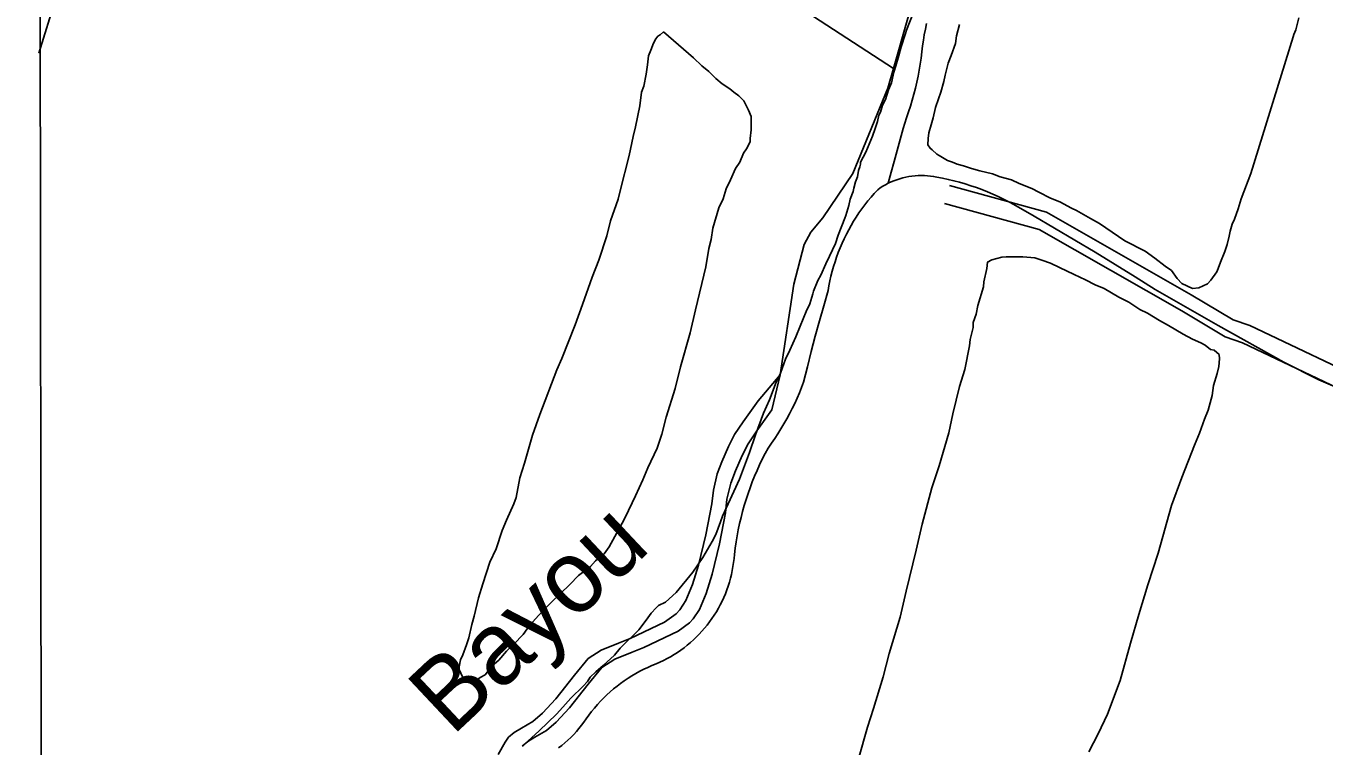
# Model space of a CAD drawing. Extents: x 3329332 to 3367211, y 631066 to 656469.
# Drawn here: x 3333430 to 3335509, y 637897 to 639050 of the extents above; entities that cross this region are included whole.
import ezdxf

# ---------------------------------------------------------------- set-up
doc = ezdxf.new("R2010")
doc.units = 0
for name, color, linetype in [('V-DTCH-CNTR', 7, 'Continuous'), ('V-GRID-FRAM', 7, 'Continuous'), ('V-RIVR-IDEN', 7, 'Continuous'), ('V-ROAD-CNTR', 7, 'Continuous'), ('V-SITE-VEGE', 7, 'Continuous'), ('V-TOPO-SHOR', 7, 'Continuous')]:
    doc.layers.add(name, color=color, linetype=linetype)

msp = doc.modelspace()

# ---------------------------------------------------------------- linework, layer by layer
at = {"layer": 'V-DTCH-CNTR'}
for points in [[(3334810.8, 638798.4), (3334815.4, 638816), (3334820.1, 638833.5), (3334824.8, 638851), (3334829.7, 638868.5), (3334834.7, 638886), (3334839.8, 638903.4), (3334843.1, 638912.7), (3334846.2, 638922.1), (3334849.2, 638931.5), (3334851.9, 638941), (3334854.3, 638950.5), (3334856.6, 638960.1), (3334858.7, 638969.8), (3334860.5, 638979.5), (3334862.1, 638989.2), (3334863.6, 638999), (3334864.7, 639008.8), (3334865.7, 639018.6), (3334867, 639027.5), (3334868.5, 639036.4), (3334870.3, 639045.3), (3334872.2, 639054.1)], [(3335238.4, 638628.4), (3335206.4, 638648.4), (3335174.3, 638668.2), (3335142, 638687.9), (3335109.7, 638707.3), (3335077.2, 638726.5), (3335044.6, 638745.6), (3335011.9, 638764.4), (3335003.6, 638768.9), (3334995.3, 638773.2), (3334986.8, 638777.3), (3334978.2, 638781.2), (3334969.5, 638784.8), (3334960.8, 638788.3), (3334952, 638791.6), (3334943.1, 638794.6), (3334934.1, 638797.4), (3334925, 638800.1), (3334915.9, 638802.5), (3334906.8, 638804.6), (3334897.6, 638806.6), (3334888.3, 638808.4), (3334883.4, 638809.3), (3334878.5, 638810), (3334873.6, 638810.5), (3334868.6, 638810.8), (3334863.6, 638810.9), (3334858.7, 638810.8), (3334853.7, 638810.4), (3334848.7, 638809.9), (3334843.8, 638809.2), (3334838.9, 638808.2), (3334834.1, 638807.1), (3334829.3, 638805.7), (3334824.6, 638804.2), (3334819.9, 638802.5), (3334815.3, 638800.5), (3334810.8, 638798.4), (3334806.4, 638796.1), (3334802.1, 638793.6), (3334797.9, 638790.9), (3334793.8, 638788.1), (3334788.4, 638782.3), (3334783.2, 638776.3), (3334778.1, 638770.2), (3334773.2, 638763.9), (3334768.5, 638757.5), (3334763.9, 638751), (3334759.5, 638744.4), (3334755.3, 638737.7), (3334751.2, 638730.8), (3334747.4, 638723.9), (3334743.7, 638716.8), (3334740.2, 638709.7), (3334736.8, 638702.5), (3334733.7, 638695.2), (3334730.8, 638687.8), (3334728, 638680.3), (3334725.5, 638672.8), (3334723.1, 638665.2), (3334721, 638657.6), (3334719, 638649.9), (3334717.3, 638642.1), (3334715.7, 638634.3), (3334714.4, 638626.5)], [(3334714.4, 638626.5), (3334707.4, 638602.2), (3334700.5, 638577.9), (3334693.9, 638553.5), (3334687.4, 638529.1), (3334681.2, 638504.7), (3334675, 638480.2), (3334671.8, 638471.5), (3334668.4, 638462.9), (3334664.8, 638454.3), (3334661, 638445.9), (3334657, 638437.5), (3334652.8, 638429.3), (3334648.4, 638421.1), (3334643.8, 638413.1), (3334639, 638405.1), (3334634.1, 638397.3), (3334628.9, 638389.6), (3334623.6, 638382), (3334618.2, 638374.5), (3334613.5, 638365.7), (3334609, 638356.8), (3334604.7, 638347.8), (3334600.6, 638338.7), (3334596.7, 638329.5), (3334593, 638320.2), (3334589.5, 638310.8), (3334586.2, 638301.4), (3334583.1, 638291.9), (3334580.2, 638282.4), (3334577.5, 638272.8), (3334575, 638263.1), (3334572.7, 638253.4), (3334570.6, 638243.6), (3334568.7, 638233.8), (3334567, 638224), (3334565.6, 638214.1), (3334564.3, 638204.2), (3334563.8, 638197.7), (3334563.1, 638191.3), (3334562.1, 638184.9), (3334561, 638178.5), (3334559.6, 638172.1), (3334558.1, 638165.8), (3334556.4, 638159.6), (3334554.4, 638153.4), (3334552.3, 638147.3), (3334550, 638141.2), (3334547.4, 638135.2), (3334544.7, 638129.3), (3334541.8, 638123.5), (3334538.8, 638117.8), (3334535.5, 638112.2), (3334532.1, 638106.7), (3334528.5, 638101.3), (3334524.7, 638096), (3334520.8, 638090.9), (3334516.7, 638085.9), (3334512.4, 638081), (3334508, 638076.2), (3334503.4, 638071.6), (3334498.7, 638067.1), (3334493.9, 638062.8), (3334488.9, 638058.7), (3334483.8, 638054.7), (3334478.6, 638050.8), (3334473.2, 638047.1), (3334467.8, 638043.7), (3334462.2, 638040.3), (3334456.5, 638037.2), (3334450.8, 638034.2), (3334444.9, 638031.4), (3334439, 638028.9), (3334432.3, 638026.2), (3334425.7, 638023.2), (3334419.1, 638020.1), (3334412.7, 638016.9), (3334406.4, 638013.4), (3334400.2, 638009.7), (3334394.1, 638005.9), (3334388.1, 638001.8), (3334382.2, 637997.6), (3334376.5, 637993.2), (3334370.9, 637988.7), (3334365.4, 637984), (3334360.1, 637979.1), (3334354.9, 637974.1), (3334349.8, 637968.9), (3334345, 637963.6), (3334340.2, 637958.1), (3334335.7, 637952.5), (3334331.3, 637946.8), (3334327.1, 637940.9), (3334323.4, 637935.6), (3334319.6, 637930.4), (3334315.5, 637925.4)], [(3335238.4, 638628.4), (3335339.3, 638570.5), (3335444.3, 638511.7), (3335500.3, 638483.7), (3335530.1, 638470.7), (3335576.5, 638452.5), (3335626.4, 638433.6), (3335714.4, 638405.1), (3335800.5, 638379.4), (3335853.2, 638361.9)], [(3334315.5, 637925.4), (3334311.3, 637920.4), (3334307, 637915.7), (3334302.5, 637911), (3334297.8, 637906.6), (3334293, 637902.2), (3334288, 637898.1), (3334282.9, 637894.1)]]:
    msp.add_lwpolyline(points, dxfattribs=at)
at = {"layer": 'V-GRID-FRAM'}
msp.add_lwpolyline([(3333429.9, 654632), (3364987.9, 654691.7), (3365030.2, 636507.7), (3333456.4, 636448), (3333429.9, 654632)], dxfattribs=at)
at = {"layer": 'V-ROAD-CNTR'}
for points in [[(3333450.3, 639006.7), (3333532.2, 639270.1), (3333696.4, 639772.9), (3333708.4, 639832.1), (3333708.2, 639866.7), (3333693, 639907.9), (3333671.2, 639941.2), (3333642, 639975.6), (3333448.6, 640213.1)], [(3333450.3, 639006.7), (3333450.3, 639006.7)], [(3333450.3, 639006.7), (3333450.3, 639006.7)], [(3333450.3, 639006.7), (3333450.3, 639006.7)], [(3333450.3, 639006.7), (3333450.3, 639006.7)], [(3333450.3, 639006.7), (3333450.3, 639006.7)], [(3333450.3, 639006.7), (3333450.3, 639006.7)], [(3333450.3, 639006.7), (3333450.3, 639006.7)], [(3333450.3, 639006.7), (3333450.3, 639006.7)], [(3334908.9, 638794.7), (3335064.2, 638752.3), (3335295.8, 638620), (3335363.2, 638579.9), (3335389.5, 638570.7), (3335596.2, 638472.2), (3335773.9, 638408.5), (3335858, 638383.2), (3335928.9, 638357.3), (3336079.5, 638310.9), (3336242.2, 638252.3), (3336363.2, 638197.5), (3336453.2, 638180.6), (3336572, 638138.2), (3336799.2, 638066.7), (3337035.2, 637993.3), (3337050.7, 637983.7)], [(3334901, 638765.8), (3335052.6, 638724.4), (3335280.7, 638594.1), (3335350.5, 638552.6), (3335378.1, 638542.9), (3335584.7, 638444.5), (3335764.5, 638380), (3335848.5, 638354.7), (3335919.4, 638328.9), (3336070, 638282.4), (3336230.9, 638224.5), (3336354.1, 638168.7), (3336445.4, 638151.6), (3336562.5, 638109.8), (3336790.2, 638038.1), (3337022.6, 637965.8), (3337032.8, 637959.5)]]:
    msp.add_lwpolyline(points, dxfattribs=at)
at = {"layer": 'V-SITE-VEGE'}
for p, q in [((3333455.7, 636954.7), (3333452.1, 639386.2)), ((3334850.4, 639070.8), (3334839.8, 639043.8)), ((3334445.4, 639036.3), (3334441.9, 639034.1)), ((3334451.1, 639040.7), (3334445.4, 639036.3)), ((3334499, 638999.3), (3334451.1, 639040.7)), ((3334838.6, 639038.2), (3334831.5, 639016.8)), ((3334839.8, 639043.8), (3334838.6, 639038.2)), ((3334435, 639022.9), (3334430.3, 639011.7)), ((3334438.5, 639029.6), (3334435, 639022.9)), ((3334441.9, 639034.1), (3334438.5, 639029.6)), ((3334831.5, 639016.8), (3334827.9, 639003.3)), ((3334426.8, 639002.7), (3334425.4, 638988)), ((3334430.3, 639011.7), (3334426.8, 639002.7)), ((3334512.4, 638986.7), (3334499, 638999.3)), ((3334827.9, 639003.3), (3334823.1, 638986.4)), ((3334422.9, 638973.4), (3334419.2, 638954.2)), ((3334425.4, 638988), (3334422.9, 638973.4)), ((3334523.6, 638977.5), (3334512.4, 638986.7)), ((3334534.7, 638966), (3334523.6, 638977.5)), ((3334819.6, 638976.3), (3334816, 638959.4)), ((3334823.1, 638986.4), (3334819.6, 638976.3)), ((3334419.2, 638954.2), (3334415.7, 638944.1)), ((3334544.7, 638957.9), (3334534.7, 638966)), ((3334557, 638949.8), (3334544.7, 638957.9)), ((3334816, 638959.4), (3334811.3, 638948.2)), ((3334415.7, 638944.1), (3334413.1, 638922.7)), ((3334563.7, 638944.1), (3334557, 638949.8)), ((3334571.5, 638938.3), (3334563.7, 638944.1)), ((3334579.3, 638930.3), (3334571.5, 638938.3)), ((3334806.5, 638932.4), (3334801.8, 638923.5)), ((3334811.3, 638948.2), (3334806.5, 638932.4)), ((3334413.1, 638922.7), (3334405.8, 638888.9)), ((3334587, 638915.5), (3334579.3, 638930.3)), ((3334591.4, 638905.2), (3334587, 638915.5)), ((3334798.3, 638912.2), (3334795.9, 638907.7)), ((3334801.8, 638923.5), (3334798.3, 638912.2)), ((3334591, 638883.8), (3334591.4, 638905.2)), ((3334793.5, 638897.6), (3334790, 638886.4)), ((3334795.9, 638907.7), (3334793.5, 638897.6)), ((3334402.2, 638873.1), (3334396.1, 638842.7)), ((3334405.8, 638888.9), (3334402.2, 638873.1)), ((3334589.6, 638864.6), (3334589.7, 638870.2)), ((3334589.7, 638870.2), (3334591, 638883.8)), ((3334785.3, 638874), (3334774.7, 638848.2)), ((3334790, 638886.4), (3334785.3, 638874)), ((3334579.2, 638846.7), (3334583.8, 638853.4)), ((3334583.8, 638853.4), (3334589.6, 638864.6)), ((3334774.7, 638848.2), (3334766.5, 638832.5)), ((3334396.1, 638842.7), (3334381.6, 638786.4)), ((3334566.4, 638822), (3334573.3, 638832.1)), ((3334573.3, 638832.1), (3334579.2, 638846.7)), ((3334766.5, 638829.1), (3334765.3, 638824.6)), ((3334766.5, 638832.5), (3334766.5, 638829.1)), ((3334558.2, 638804), (3334566.4, 638822)), ((3334761.7, 638808.8), (3334758.1, 638801)), ((3334762.9, 638819), (3334761.7, 638808.8)), ((3334765.3, 638824.6), (3334762.9, 638819)), ((3334381.6, 638786.4), (3334378, 638772.9)), ((3334546.4, 638773.7), (3334551.2, 638789.5)), ((3334551.2, 638789.5), (3334558.2, 638804)), ((3334754.5, 638785.2), (3334749.8, 638772.9)), ((3334755.7, 638790.8), (3334754.5, 638785.2)), ((3334758.1, 638801), (3334755.7, 638790.8)), ((3334378, 638772.9), (3334366.2, 638738.1)), ((3334539.4, 638759.1), (3334546.4, 638773.7)), ((3334749.8, 638772.9), (3334747.4, 638762.7)), ((3334529.9, 638726.5), (3334539.4, 638759.1)), ((3334742.6, 638747), (3334741.4, 638742.5)), ((3334747.4, 638762.7), (3334742.6, 638747)), ((3334366.2, 638738.1), (3334360.2, 638714.4)), ((3334527.3, 638708.5), (3334529.9, 638726.5)), ((3334741.4, 638742.5), (3334730.8, 638715.5)), ((3334360.2, 638714.4), (3334347.1, 638675.1)), ((3334523.7, 638693.8), (3334527.3, 638708.5)), ((3334726.1, 638702), (3334716.8, 638681.8)), ((3334730.8, 638715.5), (3334726.1, 638702)), ((3334518.7, 638664.5), (3334523.7, 638693.8)), ((3334716.8, 638681.8), (3334710.9, 638669.5)), ((3334347.1, 638675.1), (3334336.6, 638648.1)), ((3334501.9, 638595.9), (3334518.7, 638664.5)), ((3334710.9, 638669.5), (3334702.7, 638651.5)), ((3334336.6, 638648.1), (3334321.2, 638604.3)), ((3334698.1, 638642.6), (3334691, 638625.7)), ((3334702.7, 638651.5), (3334698.1, 638642.6)), ((3334689.8, 638621.2), (3334685.1, 638605.5)), ((3334691, 638625.7), (3334689.8, 638621.2)), ((3334321.2, 638604.3), (3334309.4, 638571.7)), ((3334685.1, 638605.5), (3334679.2, 638593.1)), ((3334493.4, 638558.7), (3334501.9, 638595.9)), ((3334679.2, 638593.1), (3334669.8, 638569.5)), ((3334309.4, 638571.7), (3334288.2, 638517.8)), ((3334477.9, 638504.7), (3334493.4, 638558.7)), ((3334669.8, 638569.5), (3334662.8, 638552.7)), ((3334662.8, 638552.7), (3334653.4, 638531.4)), ((3334288.2, 638517.8), (3334280, 638499.8)), ((3334646.4, 638516.8), (3334638.2, 638494.3)), ((3334653.4, 638531.4), (3334646.4, 638516.8)), ((3334280, 638499.8), (3334252.9, 638427.9)), ((3334469.4, 638469.8), (3334477.9, 638504.7)), ((3334638.2, 638494.3), (3334631.2, 638479.7)), ((3334631.2, 638479.7), (3334620.6, 638451.7)), ((3334455.2, 638423.7), (3334469.4, 638469.8)), ((3334620.6, 638451.7), (3334611.2, 638430.3)), ((3334252.9, 638427.9), (3334241.1, 638395.3)), ((3334448, 638396.7), (3334455.2, 638423.7)), ((3334611.2, 638430.3), (3334598.2, 638395.5)), ((3334241.1, 638395.3), (3334228, 638350.3)), ((3334440.8, 638374.2), (3334448, 638396.7)), ((3334598.2, 638395.5), (3334588.8, 638367.4)), ((3334425.7, 638342.8), (3334440.8, 638374.2)), ((3334228, 638350.3), (3334220.9, 638326.7)), ((3334588.8, 638367.4), (3334572.3, 638324.7)), ((3334417.5, 638323.7), (3334425.7, 638342.8)), ((3334220.9, 638326.7), (3334214.7, 638295.2)), ((3334405.8, 638297.9), (3334417.5, 638323.7)), ((3334572.3, 638324.7), (3334545.4, 638265.2)), ((3334214.7, 638295.2), (3334211.2, 638285)), ((3334389.4, 638263.1), (3334405.8, 638297.9)), ((3334211.2, 638285), (3334199.5, 638259.2)), ((3334199.5, 638259.2), (3334192.5, 638242.4)), ((3334363.8, 638216), (3334384.8, 638254.1)), ((3334384.8, 638254.1), (3334389.4, 638263.1)), ((3334541.9, 638256.2), (3334534.8, 638236)), ((3334545.4, 638265.2), (3334541.9, 638256.2)), ((3334192.5, 638242.4), (3334183, 638213.2)), ((3334528.9, 638224.8), (3334513.9, 638199)), ((3334534.8, 638236), (3334528.9, 638224.8)), ((3334183, 638213.2), (3334172.5, 638191.9)), ((3334342, 638193.8), (3334355.7, 638204.9)), ((3334355.7, 638204.9), (3334363.8, 638216)), ((3334172.5, 638191.9), (3334161.8, 638157)), ((3334314.5, 638170.5), (3334334, 638184.9)), ((3334334, 638184.9), (3334342, 638193.8)), ((3334513.9, 638199), (3334497.7, 638175.6)), ((3334300.8, 638156), (3334314.5, 638170.5)), ((3334497.7, 638175.6), (3334471.2, 638143.2)), ((3334161.8, 638157), (3334154.6, 638134.5)), ((3334270.9, 638127.1), (3334300.8, 638156)), ((3334471.2, 638143.2), (3334454, 638127.6)), ((3334154.6, 638134.5), (3334147.4, 638105.2)), ((3334251.4, 638107), (3334270.9, 638127.1)), ((3334442.6, 638122.2), (3334439.2, 638118.8)), ((3334454, 638127.6), (3334442.6, 638122.2)), ((3334147.4, 638105.2), (3334143.8, 638091.7)), ((3334236.5, 638090.3), (3334251.4, 638107)), ((3334431.1, 638109.9), (3334423, 638098.7)), ((3334439.2, 638118.8), (3334431.1, 638109.9)), ((3334143.8, 638091.7), (3334139, 638070.3)), ((3334226.1, 638075.8), (3334236.5, 638090.3)), ((3334411.5, 638083.1), (3334381.7, 638054.2)), ((3334423, 638098.7), (3334411.5, 638083.1)), ((3334135.4, 638059.1), (3334129.5, 638043.3)), ((3334139, 638070.3), (3334135.4, 638059.1)), ((3334199.7, 638049.1), (3334211.1, 638060.2)), ((3334211.1, 638060.2), (3334226.1, 638075.8)), ((3334129.5, 638043.3), (3334126, 638035.5)), ((3334187, 638034.6), (3334199.7, 638049.1)), ((3334372.5, 638043), (3334354.1, 638026.3)), ((3334381.7, 638054.2), (3334372.5, 638043)), ((3334123.6, 638024.2), (3334123.5, 638019.7)), ((3334123.5, 638019.7), (3334129, 638008.3)), ((3334126, 638035.5), (3334123.6, 638024.2)), ((3334165.2, 638011.2), (3334176.7, 638025.7)), ((3334176.7, 638025.7), (3334187, 638034.6)), ((3334342.7, 638016.3), (3334333.5, 638007.4)), ((3334354.1, 638026.3), (3334342.7, 638016.3)), ((3334129, 638008.3), (3334134.5, 638001.5)), ((3334134.5, 638001.5), (3334144.7, 638000.2)), ((3334144.7, 638000.2), (3334149.2, 638001.2)), ((3334149.2, 638001.2), (3334157.2, 638006.8)), ((3334157.2, 638006.8), (3334165.2, 638011.2)), ((3334328.9, 638000.7), (3334322, 637992.9)), ((3334333.5, 638007.4), (3334328.9, 638000.7)), ((3334322, 637992.9), (3334302.5, 637974)), ((3334289.8, 637959.5), (3334279.5, 637948.4)), ((3334302.5, 637974), (3334289.8, 637959.5)), ((3334279.5, 637948.4), (3334252, 637921.7)), ((3334252, 637921.7), (3334233.6, 637905)), ((3334233.6, 637905), (3334225.6, 637897.2))]:
    msp.add_line(p, q, dxfattribs=at)
for points in [[(3335468.4, 639063.5), (3335463.6, 639044.4), (3335460.1, 639036.5), (3335458.9, 639033.2), (3335391.2, 638813.9), (3335375.8, 638773.4), (3335371.1, 638757.7), (3335365.2, 638740.8), (3335361.7, 638732.9), (3335358.1, 638721.7), (3335356.8, 638713.8), (3335353.3, 638700.3), (3335349.7, 638689.1), (3335342.6, 638672.2), (3335339.1, 638662.1), (3335336.8, 638656.5), (3335327.5, 638643.1), (3335321.8, 638637.5), (3335308.1, 638630.9), (3335297.9, 638630), (3335281.1, 638638.1), (3335273.3, 638646.2), (3335264.5, 638658.7), (3335254.4, 638665.7), (3335237.7, 638678.3), (3335222, 638689.9), (3335189.5, 638706.2), (3335149.2, 638733.9), (3335134.7, 638742.1), (3335112.3, 638754.9), (3335104.4, 638758.4), (3335085.4, 638768.8), (3335070.8, 638774.7), (3335051.7, 638784), (3335040.5, 638789.9), (3335020.3, 638798.1), (3335007.9, 638803.9), (3334989.9, 638808.7), (3334977.6, 638813.4), (3334957.3, 638818.3), (3334943.8, 638821.9), (3334931.4, 638826.6), (3334921.3, 638829), (3334913.4, 638832.5), (3334905.6, 638834.9), (3334892.1, 638843), (3334888.8, 638845.3), (3334881, 638852.2), (3334877.6, 638854.5), (3334874.3, 638860.2), (3334874.5, 638870.4), (3334875.7, 638879.4), (3334879.3, 638891.8), (3334882.9, 638903), (3334886.5, 638919.9), (3334891.3, 638933.4), (3334894.8, 638944.6), (3334899.6, 638961.5), (3334902, 638971.7), (3334906.8, 638990.8), (3334911.5, 639003.2), (3334918.6, 639022.3), (3334919.9, 639034.7), (3334924.7, 639052.7)], [(3334763.2, 637876.5), (3334777.5, 637927.2), (3334787, 637957.5), (3334802.5, 638008.1), (3334812.1, 638045.3), (3334829.9, 638103.8), (3334839.6, 638145.4), (3334855.3, 638210.7), (3334865, 638252.4), (3334880.6, 638310.9), (3334892.4, 638345.8), (3334907.9, 638398.6), (3334914, 638429.1), (3334924.9, 638473), (3334933.2, 638500), (3334940.6, 638538.3), (3334941.9, 638548.4), (3334946.7, 638567.6), (3334946.8, 638575.5), (3334951.5, 638589), (3334954, 638602.5), (3334963.5, 638632.8), (3334963.6, 638640.7), (3334968.5, 638662.1), (3334969.7, 638672.3), (3334976.6, 638675.6), (3334992.5, 638679.9), (3334999.3, 638680.9), (3335026.4, 638680.5), (3335045.6, 638679), (3335056.8, 638675.5), (3335070.3, 638670.7), (3335084.9, 638663.7), (3335108.4, 638652.1), (3335126.4, 638643.9), (3335142.1, 638635.7), (3335156.7, 638629.9), (3335180.2, 638615.9), (3335195.9, 638607.8), (3335213.8, 638596.2), (3335226.1, 638590.4), (3335245.2, 638578.8), (3335259.7, 638570.7), (3335283.2, 638556.7), (3335297.8, 638548.6), (3335311.3, 638542.7), (3335318, 638539.3), (3335326.9, 638532.3), (3335332.6, 638531.1), (3335340.4, 638524.2), (3335341.4, 638517.4), (3335340.1, 638505), (3335337.6, 638493.7), (3335331.7, 638474.6), (3335329.2, 638458.8), (3335323.2, 638435.2), (3335317.3, 638420.6), (3335309.1, 638398.1), (3335300.9, 638379.1), (3335280.9, 638327.4), (3335264.3, 638282.4), (3335242.8, 638205.9), (3335226.2, 638155.3), (3335211.9, 638108.1), (3335198.8, 638062), (3335182.1, 638002.3), (3335162, 637948.4), (3335146.9, 637917), (3335131.7, 637887.8)]]:
    msp.add_lwpolyline(points, dxfattribs=at)
at = {"layer": 'V-TOPO-SHOR'}
for q in [(3334602.6, 638449.9), (3334624.3, 638435.5)]:
    msp.add_line((3334637.5, 638491.8), q, dxfattribs=at)
for points in [[(3333748.9, 639741), (3333820.8, 639664.7), (3333977.1, 639502.6), (3334108.7, 639373.5), (3334215.8, 639296.1), (3334247.6, 639278.7), (3334349.5, 639236.4), (3334484.9, 639179.1), (3334601.5, 639126.6), (3334658.9, 639086.3), (3334819, 638982.5)], [(3335520.6, 639361.6), (3335481, 639394), (3335456.1, 639403.6), (3335378.9, 639409.7), (3335304.7, 639400.1), (3335217.8, 639368.9), (3335127.8, 639345.4), (3335068.4, 639335.8), (3335016, 639317.5), (3334946.1, 639268.9), (3334906, 639227.9), (3334886.9, 639193.7), (3334866.3, 639148.6), (3334842.1, 639063), (3334819, 638982.5), (3334810, 638950.8), (3334754.2, 638813.9), (3334706, 638743.3), (3334687, 638720.1), (3334676, 638700.6), (3334659.8, 638636.8), (3334637.5, 638491.8)], [(3334602.6, 638449.9), (3334578.6, 638416.6), (3334564.7, 638395.9), (3334554.9, 638377), (3334544.2, 638352.2), (3334537, 638332.9), (3334530.7, 638307), (3334528.2, 638285), (3334518.6, 638235.7), (3334506.9, 638186.7), (3334497.2, 638156.1), (3334486.6, 638130.2), (3334476.8, 638115.3), (3334470.9, 638109.2), (3334452.3, 638095.6), (3334397.7, 638069.3), (3334378.9, 638062.2), (3334351.2, 638050.9), (3334330.4, 638037.3), (3334308.4, 638010.9), (3334278.5, 637972.9), (3334257.3, 637949.7), (3334241.7, 637936.4), (3334223.2, 637925.7), (3334211.7, 637918.9), (3334202.8, 637911.7), (3334197.2, 637903.4), (3334186.2, 637883.7)], [(3334624.3, 638435.5), (3334600.4, 638402.1), (3334586.5, 638381.4), (3334576.7, 638362.5), (3334566, 638337.7), (3334558.7, 638318.4), (3334552.5, 638292.5), (3334549.9, 638270.5), (3334540.4, 638221.2), (3334528.6, 638172.3), (3334519, 638141.6), (3334508.3, 638115.7), (3334498.6, 638100.9), (3334492.6, 638094.7), (3334474.1, 638081.1), (3334419.4, 638054.8), (3334400.6, 638047.7), (3334373, 638036.4), (3334352.2, 638022.8), (3334330.2, 637996.4), (3334300.3, 637958.4), (3334279, 637935.2), (3334263.4, 637921.9), (3334244.9, 637911.2), (3334233.5, 637904.4), (3334224.6, 637897.2)]]:
    msp.add_lwpolyline(points, dxfattribs=at)

# ---------------------------------------------------------------- texts
at = {"layer": 'V-RIVR-IDEN'}
msp.add_text('Bayou', height=116, rotation=43.1913, dxfattribs=at).set_placement((3334112.3, 637911.8))

doc.saveas('drawing.dxf')
